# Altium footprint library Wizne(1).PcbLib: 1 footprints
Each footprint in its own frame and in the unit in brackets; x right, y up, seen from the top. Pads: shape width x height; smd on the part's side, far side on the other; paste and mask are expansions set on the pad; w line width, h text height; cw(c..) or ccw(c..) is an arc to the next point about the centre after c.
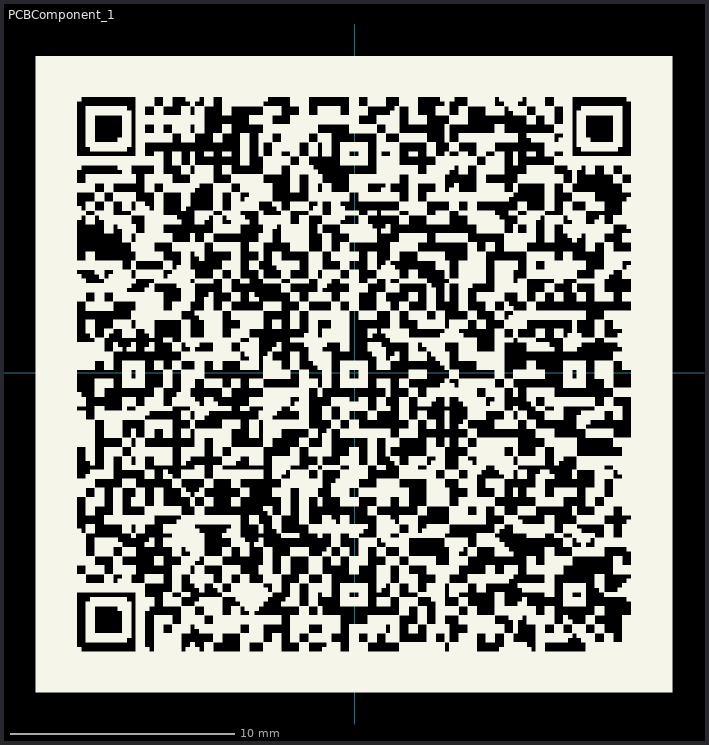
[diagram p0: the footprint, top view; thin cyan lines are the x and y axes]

## PCBComponent_1 [mm]
Top Overlay:
  drawing of 17208 lines, arcs and shapes, not listed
